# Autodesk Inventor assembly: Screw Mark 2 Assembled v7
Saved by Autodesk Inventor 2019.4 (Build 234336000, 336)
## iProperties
Created: 2020-06
Part Number: Screw Mark 2 Assembled v7
Document SubType Name: Assembly
Designer: Administrator
Title: Screw Mark 2 Assembled v7
Author: Administrator
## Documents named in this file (15)
- c:\worker\convert-fusion-r04\tmp\job-1\85\output\files\12fc5e84-6763-4458-a53a-9d1ae2180744\Screw Mark 2 Assembled v7.iam
- c:\worker\convert-fusion-r04\tmp\job-1\85\output\files\12fc5e84-6763-4458-a53a-9d1ae2180744\001 Roller v3.ipt
- c:\worker\convert-fusion-r04\tmp\job-1\85\output\files\12fc5e84-6763-4458-a53a-9d1ae2180744\Upgraded Screw Harry Edited v15.ipt
- c:\worker\convert-fusion-r04\tmp\job-1\85\output\files\12fc5e84-6763-4458-a53a-9d1ae2180744\Component1_1.ipt
- c:\worker\convert-fusion-r04\tmp\job-1\85\output\files\12fc5e84-6763-4458-a53a-9d1ae2180744\Component2.ipt
- c:\worker\convert-fusion-r04\tmp\job-1\85\output\files\12fc5e84-6763-4458-a53a-9d1ae2180744\Component3.ipt
- c:\worker\convert-fusion-r04\tmp\job-1\85\output\files\12fc5e84-6763-4458-a53a-9d1ae2180744\Component4.ipt
- c:\worker\convert-fusion-r04\tmp\job-1\85\output\files\12fc5e84-6763-4458-a53a-9d1ae2180744\Component5.ipt
- c:\worker\convert-fusion-r04\tmp\job-1\85\output\files\12fc5e84-6763-4458-a53a-9d1ae2180744\Component6.ipt
- c:\worker\convert-fusion-r04\tmp\job-1\85\output\files\12fc5e84-6763-4458-a53a-9d1ae2180744\Component7.ipt
- c:\worker\convert-fusion-r04\tmp\job-1\85\output\files\12fc5e84-6763-4458-a53a-9d1ae2180744\Component8.ipt
- c:\worker\convert-fusion-r04\tmp\job-1\85\output\files\12fc5e84-6763-4458-a53a-9d1ae2180744\Component9.ipt
- c:\worker\convert-fusion-r04\tmp\job-1\85\output\files\12fc5e84-6763-4458-a53a-9d1ae2180744\Component10.ipt
- c:\worker\convert-fusion-r04\tmp\job-1\85\output\files\12fc5e84-6763-4458-a53a-9d1ae2180744\Component11.ipt
- c:\worker\convert-fusion-r04\tmp\job-1\85\output\files\12fc5e84-6763-4458-a53a-9d1ae2180744\Component12.ipt
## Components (25 placed, 14 different names)
1. 001 Roller v3:1
2. 001 Roller v3:2
3. 001 Roller v3:3
4. 001 Roller v3:4
5. 001 Roller v3:5
6. 001 Roller v3:6
7. 001 Roller v3:7
8. 001 Roller v3:8
9. 001 Roller v3:9
10. 001 Roller v3:10
11. 001 Roller v3:11
12. 001 Roller v3:12
13. Upgraded Screw Harry Edited v15:1
14. Component1:1
15. Component2:1
16. Component3:1
17. Component4:1
18. Component5:1
19. Component6:1
20. Component7:1
21. Component8:1
22. Component9:1
23. Component10:1
24. Component11:1
25. Component12:1
